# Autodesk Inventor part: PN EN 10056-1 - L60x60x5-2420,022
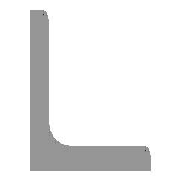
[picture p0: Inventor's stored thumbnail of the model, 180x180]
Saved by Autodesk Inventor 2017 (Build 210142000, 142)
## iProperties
_CCFamilyMember: 130
_CCFamilyDisplayName: PN EN 10056-1 (Kątownik równoramienny) - Kątownik równoramienny
_FrameMemberDoc: Frame Member File
_Version: 15.0.0
_GetPNFromCC: 1
Created: 2016-02
Part Number: PN EN 10056-1 - L60x60x5-2420,022
Material: Stal, miękka
Description: Kątownik równoramienny
Document SubType Name: Modeling
Standard: PN
Designer: X
Standards Organization: PN
Language: pl-PL
Size Designation: L60x60x5
Categories: <MemberInstance><Categories><Category DisplayName="Kształtowniki konstrukcyjne" InternalName="089c4875-fa83-4c05-b084-43b9cc11f5ed" Mnemonic="GRDR"><CategoryPar
Stock Number: L60x60x5
Density: 7.85 g/cm^3
Appearance: Częściowo polerowana
Mass: 11053.8 g
Surface Area: 5653.5 cm^2
Volume: 1408.13 cm^3
IsCustomPart: 1
G_W: 60,000 mm
G_H: 60,000 mm
G_L: 2420,022 mm
Author: X
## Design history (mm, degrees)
node "Płaszczyzna początkowa"
node "Płaszczyzna końcowa"
sketch "Szkic"
  geometry: L1 (-11.517, -3.517)-(-11.517, 39.483); L2 (-16.517, 43.483)-(-15.517, 43.483); L3 (-16.517, -16.517)-(-16.517, 43.483); L4 (-16.517, -16.517)-(43.483, -16.517); L5 (43.483, -15.517)-(43.483, -16.517); L6 (-3.517, -11.517)-(39.483, -11.517); L7 (0, 56.477)-(0, -28.683) reference; L8 (-28.683, 0)-(56.477, 0) reference; A1 r 8 centre (-3.517, -3.517) between (-11.517, -3.517) and (-3.517, -11.517); A2 r 4 centre (-15.517, 39.483) between (-11.517, 39.483) and (-15.517, 43.483); A3 r 4 centre (39.483, -15.517) between (43.483, -15.517) and (39.483, -11.517); 3 further points
  constraints: 12 end point, 6 point on circle, 6 point on line, 6 tangent, 3 centre point, 3 horizontal, 3 vertical, 1 equal radius
  dimensions: "d4" = 60 distance of L3.start L4.end (= b); "d6" = 60 distance of L3.start L2.start (= b); "d8" = 5 distance of point (43.483, -11.517) L4.end (= ParT); "d10" = 5 distance of L2.start point (-11.517, 43.483) (= ParT); "d17" = 8 radius of A1 (= R); "d18" = 4 radius of A2 (= R1); "d19" = 16.51748 distance between parallel lines of L8 L4 (= ex); "d20" = 16.51748 distance between parallel lines of L3 L7 (= d19)
extrude "Bryła" new body sketch "Szkic" stored distance "d11" = 2420.02174 (= G_L); taper "d12" = 0 deg
node "Driven Length"
  sketch "Sketch3"
    geometry: L1 (0, 0)-(10, 0) reference
    constraints: 2 end point, 1 horizontal
  workplane "Work Plane10"
  sketch "Sketch4"
    geometry: L1 (-2, -60)-(12, -60) reference; L2 (-2, 2360.022)-(12, 2360.022) reference
    dimensions: "d24" = 2420.02174 distance between parallel lines of L1 L2 (derived)
body "Solid1"
other parameters: "b" = 60 [user parameter; used in 3 equation terms], "ParT" = 5 [user parameter; used in 3 equation terms], "R" = 8 [user parameter; used in 1 equation term], "R1" = 4 [user parameter; used in 1 equation term], "G_L" = 2420.02174 (= d24) [user parameter; used in 1 equation term], "d7" = 4 (derived), "d9" = 4 (derived), "ex" = 16.51748 (computed from b, ParT) [user parameter; used in 1 equation term], "d22" = 2360.02174 (= G_OFFSET_END + B_L), "B_L" = 2300.02174 [user parameter; used in 1 equation term], "d23" = 90 deg
